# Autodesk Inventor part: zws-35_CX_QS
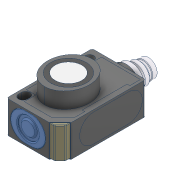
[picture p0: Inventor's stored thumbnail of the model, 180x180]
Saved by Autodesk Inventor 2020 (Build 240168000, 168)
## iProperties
Created: 2025-04
Part Number: zws-35_CX_QS
Material: Generisch
Description: STEP AP214
Document SubType Name: Modeling
Designer: Oliver Liedtke
Density: 1 g/cm^3
Appearance: Vorgabe
Title: zws-35_CX_QS.STEP
Revision Number: ANY
Sending System: SolidWorks 2024
Preprocessor: SwSTEP 2.0
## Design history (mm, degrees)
feature "Verrundung1"
node "Volumenkörper1"
